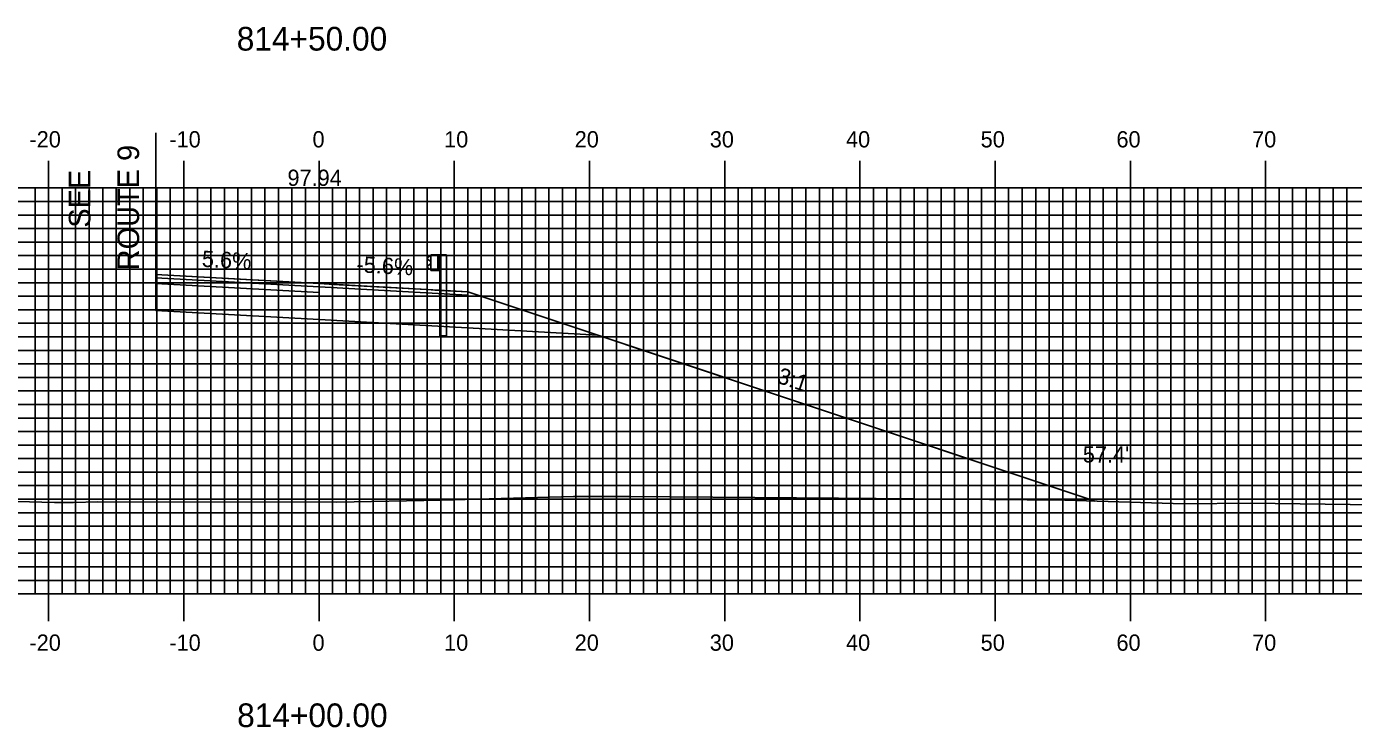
# Model space of a CAD drawing. Extents: x 2453 to 2796, y -1658 to -1438.
# Drawn here: x 2597.1 to 2695.2, y -1544.5 to -1492.7 of the extents above; entities that cross this region are included whole.
import ezdxf

# ---------------------------------------------------------------- set-up
doc = ezdxf.new("R2010")
doc.units = 0
for name, color, linetype in [('ANNOTATION', 7, 'Continuous'), ('D_Guardrail_Beam_Rt', 7, 'Continuous'), ('D_Roadway_Centerline', 7, 'Continuous'), ('D_Roadway_Centerline_Text', 7, 'Continuous'), ('D_Roadway_Edge_Shoulder', 7, 'Continuous'), ('D_Roadway_Edge_TW', 7, 'Continuous'), ('D_Roadway_Pavement', 7, 'Continuous'), ('D_Roadway_SlopeLines', 7, 'Continuous'), ('D_Roadway_SubGrade', 7, 'Continuous'), ('D_Text_Standard', 7, 'Continuous'), ('H_V ANNOTATION', 7, 'Continuous'), ('MAJOR', 7, 'Continuous'), ('MINOR', 7, 'Continuous'), ('S_Roadway_Centerline', 7, 'Continuous')]:
    doc.layers.add(name, color=color, linetype=linetype)

msp = doc.modelspace()

# ---------------------------------------------------------------- linework, layer by layer
at = {"layer": 'D_Guardrail_Beam_Rt'}
for p, q in [((2626.881, -1509.637), (2626.737, -1509.737)), ((2626.737, -1509.88), (2626.933, -1510.016)), ((2626.933, -1510.215), (2626.737, -1510.352)), ((2626.971, -1509.616), (2626.896, -1509.631)), ((2626.966, -1510.081), (2626.966, -1510.151)), ((2626.971, -1509.533), (2627.658, -1509.533)), ((2626.971, -1510.699), (2626.971, -1509.533)), ((2627.491, -1509.533), (2627.491, -1510.699)), ((2627.596, -1509.533), (2627.596, -1510.699)), ((2627.658, -1509.533), (2628.129, -1509.533)), ((2627.658, -1509.533), (2627.658, -1510.699)), ((2628.129, -1509.533), (2628.129, -1515.533)), ((2626.737, -1510.495), (2626.881, -1510.595)), ((2626.896, -1510.601), (2626.971, -1510.616)), ((2627.658, -1510.699), (2626.971, -1510.699)), ((2627.637, -1515.533), (2627.637, -1510.699)), ((2627.637, -1515.533), (2628.129, -1515.533))]:
    msp.add_line(p, q, dxfattribs=at)
for centre, major_axis, start_param, end_param in [((2626.788, -1509.809), (-0.0877, 0), 5.323254, 7.243116), ((2626.905, -1509.671), (-0.0417, 0), 4.907132, 5.323254), ((2626.887, -1510.081), (0.0789, 0), 0, 0.959931), ((2626.887, -1510.151), (0.0789, 0), 5.323254, 6.283185), ((2626.788, -1510.423), (-0.0877, 0), 5.323254, 7.243116), ((2626.905, -1510.561), (-0.0417, 0), 0.959931, 1.376053)]:
    msp.add_ellipse(centre, major_axis=major_axis, ratio=0.995501, start_param=start_param, end_param=end_param, dxfattribs=at)
at = {"layer": 'D_Roadway_Centerline'}
msp.add_lwpolyline([(2606.636, -1510.994), (2613.287, -1511.365), (2618.7, -1511.668), (2620.183, -1511.751), (2626.7, -1512.116), (2627.254, -1512.147), (2629.7, -1512.284), (2639.315, -1515.489), (2676.093, -1527.748)], dxfattribs=at)
at = {"layer": 'D_Roadway_Edge_Shoulder'}
for points in [[(2618.7, -1511.668), (2629.7, -1512.284), (2629.7, -1512.534), (2618.7, -1511.918)], [(2618.7, -1511.668), (2626.7, -1512.116), (2626.7, -1512.116), (2629.7, -1512.284), (2629.7, -1512.534), (2618.7, -1511.918)], [(2618.7, -1511.668), (2626.7, -1512.116), (2626.7, -1512.116), (2629.7, -1512.284), (2629.7, -1512.534), (2618.7, -1511.918)], [(2618.7, -1511.668), (2629.7, -1512.284), (2629.7, -1512.534), (2618.7, -1511.918)], [(2618.7, -1511.668), (2629.7, -1512.284), (2629.7, -1512.534), (2618.7, -1511.918)]]:
    msp.add_lwpolyline(points, close=True, dxfattribs=at)
at = {"layer": 'D_Roadway_Edge_TW'}
msp.add_lwpolyline([(2606.636, -1510.994), (2618.7, -1511.668), (2618.7, -1511.918), (2606.636, -1511.244)], close=True, dxfattribs=at)
msp.add_lwpolyline([(2606.636, -1510.994), (2618.7, -1511.668), (2618.7, -1511.918), (2606.636, -1511.244)], close=True, dxfattribs=at)
msp.add_lwpolyline([(2606.636, -1510.994), (2618.7, -1511.668), (2618.7, -1511.918), (2606.636, -1511.244)], close=True, dxfattribs=at)
msp.add_lwpolyline([(2606.636, -1510.994), (2618.7, -1511.668), (2618.7, -1511.918), (2606.636, -1511.244)], close=True, dxfattribs=at)
at = {"layer": 'D_Roadway_Pavement'}
msp.add_lwpolyline([(2606.636, -1511.244), (2618.7, -1511.918), (2618.7, -1512.335), (2606.636, -1511.66)], close=True, dxfattribs=at)
msp.add_lwpolyline([(2606.636, -1511.244), (2618.7, -1511.918), (2618.7, -1512.335), (2606.636, -1511.66)], close=True, dxfattribs=at)
msp.add_lwpolyline([(2606.636, -1511.244), (2618.7, -1511.918), (2618.7, -1512.335), (2606.636, -1511.66)], close=True, dxfattribs=at)
msp.add_lwpolyline([(2606.636, -1511.244), (2618.7, -1511.918), (2618.7, -1512.335), (2606.636, -1511.66)], close=True, dxfattribs=at)
msp.add_lwpolyline([(2618.7, -1511.918), (2618.7, -1512.335)], dxfattribs=at)
msp.add_lwpolyline([(2618.7, -1511.918), (2618.7, -1512.335)], dxfattribs=at)
msp.add_lwpolyline([(2618.7, -1511.918), (2618.7, -1512.335)], dxfattribs=at)
msp.add_lwpolyline([(2618.7, -1511.918), (2618.7, -1512.335)], dxfattribs=at)
msp.add_lwpolyline([(2618.7, -1511.918), (2618.7, -1512.335)], dxfattribs=at)
msp.add_lwpolyline([(2618.7, -1511.918), (2618.7, -1512.335)], dxfattribs=at)
msp.add_lwpolyline([(2618.7, -1511.918), (2618.7, -1512.335)], dxfattribs=at)
msp.add_lwpolyline([(2618.7, -1511.918), (2618.7, -1512.335)], dxfattribs=at)
msp.add_lwpolyline([(2618.7, -1511.918), (2618.7, -1512.335)], dxfattribs=at)
msp.add_lwpolyline([(2618.7, -1511.918), (2618.7, -1512.335)], dxfattribs=at)
msp.add_lwpolyline([(2618.7, -1511.918), (2618.7, -1512.335)], dxfattribs=at)
msp.add_lwpolyline([(2618.7, -1511.918), (2618.7, -1512.335)], dxfattribs=at)
msp.add_lwpolyline([(2618.7, -1511.918), (2618.7, -1512.335)], dxfattribs=at)
msp.add_lwpolyline([(2618.7, -1511.918), (2618.7, -1512.335)], dxfattribs=at)
at = {"layer": 'D_Roadway_SlopeLines'}
msp.add_lwpolyline([(2629.7, -1512.284), (2676.093, -1527.748)], dxfattribs=at)
msp.add_lwpolyline([(2629.7, -1512.284), (2676.093, -1527.748)], dxfattribs=at)
msp.add_lwpolyline([(2629.7, -1512.284), (2676.093, -1527.748)], dxfattribs=at)
msp.add_lwpolyline([(2629.7, -1512.284), (2676.093, -1527.748)], dxfattribs=at)
at = {"layer": 'D_Roadway_SubGrade'}
msp.add_line((2606.636, -1500.521), (2606.636, -1513.66), dxfattribs=at)
for points in [[(2606.636, -1511.66), (2618.7, -1512.335), (2618.7, -1514.335), (2606.636, -1513.66)], [(2606.636, -1511.66), (2618.7, -1512.335), (2618.7, -1514.335), (2606.636, -1513.66)], [(2606.636, -1511.66), (2618.7, -1512.335), (2618.7, -1514.335), (2606.636, -1513.66)], [(2606.636, -1511.66), (2618.7, -1512.335), (2618.7, -1514.335), (2606.636, -1513.66)], [(2618.7, -1512.335), (2618.7, -1511.918), (2629.7, -1512.534), (2629.7, -1512.284), (2639.315, -1515.489), (2618.7, -1514.335)]]:
    msp.add_lwpolyline(points, close=True, dxfattribs=at)
at = {"layer": 'MAJOR'}
for p, q in [((2598.7, -1502.6), (2598.7, -1504.604)), ((2608.7, -1502.6), (2608.7, -1504.604)), ((2618.7, -1502.6), (2618.7, -1504.604)), ((2628.7, -1502.6), (2628.7, -1504.604)), ((2638.7, -1502.6), (2638.7, -1504.604)), ((2648.7, -1502.6), (2648.7, -1504.604)), ((2658.7, -1502.6), (2658.7, -1504.604)), ((2668.7, -1502.6), (2668.7, -1504.604)), ((2678.7, -1502.6), (2678.7, -1504.604)), ((2688.7, -1502.6), (2688.7, -1504.604)), ((2478.7, -1504.604), (2758.7, -1504.604)), ((2478.7, -1504.604), (2758.7, -1504.604)), ((2598.7, -1534.604), (2598.7, -1504.604)), ((2608.7, -1534.604), (2608.7, -1504.604)), ((2618.7, -1534.604), (2618.7, -1504.604)), ((2628.7, -1534.604), (2628.7, -1504.604)), ((2638.7, -1534.604), (2638.7, -1504.604)), ((2648.7, -1534.604), (2648.7, -1504.604)), ((2658.7, -1534.604), (2658.7, -1504.604)), ((2668.7, -1534.604), (2668.7, -1504.604)), ((2678.7, -1534.604), (2678.7, -1504.604)), ((2688.7, -1534.604), (2688.7, -1504.604)), ((2478.7, -1509.604), (2758.7, -1509.604)), ((2478.7, -1514.604), (2758.7, -1514.604)), ((2478.7, -1519.604), (2758.7, -1519.604)), ((2478.7, -1524.604), (2758.7, -1524.604)), ((2478.7, -1529.604), (2758.7, -1529.604)), ((2478.7, -1534.604), (2758.7, -1534.604)), ((2478.7, -1534.604), (2758.7, -1534.604)), ((2598.7, -1536.608), (2598.7, -1534.604)), ((2608.7, -1536.608), (2608.7, -1534.604)), ((2618.7, -1536.608), (2618.7, -1534.604)), ((2628.7, -1536.608), (2628.7, -1534.604)), ((2638.7, -1536.608), (2638.7, -1534.604)), ((2648.7, -1536.608), (2648.7, -1534.604)), ((2658.7, -1536.608), (2658.7, -1534.604)), ((2668.7, -1536.608), (2668.7, -1534.604)), ((2678.7, -1536.608), (2678.7, -1534.604)), ((2688.7, -1536.608), (2688.7, -1534.604))]:
    msp.add_line(p, q, dxfattribs=at)
at = {"layer": 'MINOR'}
for p, q in [((2597.7, -1534.604), (2597.7, -1504.604)), ((2599.7, -1534.604), (2599.7, -1504.604)), ((2600.7, -1534.604), (2600.7, -1504.604)), ((2601.7, -1534.604), (2601.7, -1504.604)), ((2602.7, -1534.604), (2602.7, -1504.604)), ((2603.7, -1534.604), (2603.7, -1504.604)), ((2604.7, -1534.604), (2604.7, -1504.604)), ((2605.7, -1534.604), (2605.7, -1504.604)), ((2606.7, -1534.604), (2606.7, -1504.604)), ((2607.7, -1534.604), (2607.7, -1504.604)), ((2609.7, -1534.604), (2609.7, -1504.604)), ((2610.7, -1534.604), (2610.7, -1504.604)), ((2611.7, -1534.604), (2611.7, -1504.604)), ((2612.7, -1534.604), (2612.7, -1504.604)), ((2613.7, -1534.604), (2613.7, -1504.604)), ((2614.7, -1534.604), (2614.7, -1504.604)), ((2615.7, -1534.604), (2615.7, -1504.604)), ((2616.7, -1534.604), (2616.7, -1504.604)), ((2617.7, -1534.604), (2617.7, -1504.604)), ((2619.7, -1534.604), (2619.7, -1504.604)), ((2620.7, -1534.604), (2620.7, -1504.604)), ((2621.7, -1534.604), (2621.7, -1504.604)), ((2622.7, -1534.604), (2622.7, -1504.604)), ((2623.7, -1534.604), (2623.7, -1504.604)), ((2624.7, -1534.604), (2624.7, -1504.604)), ((2625.7, -1534.604), (2625.7, -1504.604)), ((2626.7, -1534.604), (2626.7, -1504.604)), ((2627.7, -1534.604), (2627.7, -1504.604)), ((2629.7, -1534.604), (2629.7, -1504.604)), ((2630.7, -1534.604), (2630.7, -1504.604)), ((2631.7, -1534.604), (2631.7, -1504.604)), ((2632.7, -1534.604), (2632.7, -1504.604)), ((2633.7, -1534.604), (2633.7, -1504.604)), ((2634.7, -1534.604), (2634.7, -1504.604)), ((2635.7, -1534.604), (2635.7, -1504.604)), ((2636.7, -1534.604), (2636.7, -1504.604)), ((2637.7, -1534.604), (2637.7, -1504.604)), ((2639.7, -1534.604), (2639.7, -1504.604)), ((2640.7, -1534.604), (2640.7, -1504.604)), ((2641.7, -1534.604), (2641.7, -1504.604)), ((2642.7, -1534.604), (2642.7, -1504.604)), ((2643.7, -1534.604), (2643.7, -1504.604)), ((2644.7, -1534.604), (2644.7, -1504.604)), ((2645.7, -1534.604), (2645.7, -1504.604)), ((2646.7, -1534.604), (2646.7, -1504.604)), ((2647.7, -1534.604), (2647.7, -1504.604)), ((2649.7, -1534.604), (2649.7, -1504.604)), ((2650.7, -1534.604), (2650.7, -1504.604)), ((2651.7, -1534.604), (2651.7, -1504.604)), ((2652.7, -1534.604), (2652.7, -1504.604)), ((2653.7, -1534.604), (2653.7, -1504.604)), ((2654.7, -1534.604), (2654.7, -1504.604)), ((2655.7, -1534.604), (2655.7, -1504.604)), ((2656.7, -1534.604), (2656.7, -1504.604)), ((2657.7, -1534.604), (2657.7, -1504.604)), ((2659.7, -1534.604), (2659.7, -1504.604)), ((2660.7, -1534.604), (2660.7, -1504.604)), ((2661.7, -1534.604), (2661.7, -1504.604)), ((2662.7, -1534.604), (2662.7, -1504.604)), ((2663.7, -1534.604), (2663.7, -1504.604)), ((2664.7, -1534.604), (2664.7, -1504.604)), ((2665.7, -1534.604), (2665.7, -1504.604)), ((2666.7, -1534.604), (2666.7, -1504.604)), ((2667.7, -1534.604), (2667.7, -1504.604)), ((2669.7, -1534.604), (2669.7, -1504.604)), ((2670.7, -1534.604), (2670.7, -1504.604)), ((2671.7, -1534.604), (2671.7, -1504.604)), ((2672.7, -1534.604), (2672.7, -1504.604)), ((2673.7, -1534.604), (2673.7, -1504.604)), ((2674.7, -1534.604), (2674.7, -1504.604)), ((2675.7, -1534.604), (2675.7, -1504.604)), ((2676.7, -1534.604), (2676.7, -1504.604)), ((2677.7, -1534.604), (2677.7, -1504.604)), ((2679.7, -1534.604), (2679.7, -1504.604)), ((2680.7, -1534.604), (2680.7, -1504.604)), ((2681.7, -1534.604), (2681.7, -1504.604)), ((2682.7, -1534.604), (2682.7, -1504.604)), ((2683.7, -1534.604), (2683.7, -1504.604)), ((2684.7, -1534.604), (2684.7, -1504.604)), ((2685.7, -1534.604), (2685.7, -1504.604)), ((2686.7, -1534.604), (2686.7, -1504.604)), ((2687.7, -1534.604), (2687.7, -1504.604)), ((2689.7, -1534.604), (2689.7, -1504.604)), ((2690.7, -1534.604), (2690.7, -1504.604)), ((2691.7, -1534.604), (2691.7, -1504.604)), ((2692.7, -1534.604), (2692.7, -1504.604)), ((2693.7, -1534.604), (2693.7, -1504.604)), ((2694.7, -1534.604), (2694.7, -1504.604)), ((2478.7, -1505.604), (2758.7, -1505.604)), ((2478.7, -1506.604), (2758.7, -1506.604)), ((2478.7, -1507.604), (2758.7, -1507.604)), ((2478.7, -1508.604), (2758.7, -1508.604)), ((2478.7, -1510.604), (2758.7, -1510.604)), ((2478.7, -1511.604), (2758.7, -1511.604)), ((2478.7, -1512.604), (2758.7, -1512.604)), ((2478.7, -1513.604), (2758.7, -1513.604)), ((2478.7, -1515.604), (2758.7, -1515.604)), ((2478.7, -1516.604), (2758.7, -1516.604)), ((2478.7, -1517.604), (2758.7, -1517.604)), ((2478.7, -1518.604), (2758.7, -1518.604)), ((2478.7, -1520.604), (2758.7, -1520.604)), ((2478.7, -1521.604), (2758.7, -1521.604)), ((2478.7, -1522.604), (2758.7, -1522.604)), ((2478.7, -1523.604), (2758.7, -1523.604)), ((2478.7, -1525.604), (2758.7, -1525.604)), ((2478.7, -1526.604), (2758.7, -1526.604)), ((2478.7, -1527.604), (2758.7, -1527.604)), ((2478.7, -1528.604), (2758.7, -1528.604)), ((2478.7, -1530.604), (2758.7, -1530.604)), ((2478.7, -1531.604), (2758.7, -1531.604)), ((2478.7, -1532.604), (2758.7, -1532.604)), ((2478.7, -1533.604), (2758.7, -1533.604))]:
    msp.add_line(p, q, dxfattribs=at)
at = {"layer": 'S_Roadway_Centerline'}
msp.add_lwpolyline([(2590.783, -1527.622), (2599.132, -1527.855), (2600.535, -1527.836), (2602.347, -1527.801), (2620.014, -1527.814), (2627.732, -1527.673), (2637.526, -1527.417), (2641.628, -1527.416), (2657.105, -1527.524), (2673.853, -1527.681), (2682.662, -1527.946), (2687.561, -1527.907), (2700.509, -1528.071)], dxfattribs=at)

# ---------------------------------------------------------------- texts
at = {"layer": 'ANNOTATION'}
for s, height, rotation, p in [('ROUTE 9', 1.6, 90, (2605.394, -1510.688)), ('SEE', 1.6, 90, (2601.794, -1507.538)), ('5.6%', 1.2, 356.8012, (2610.013, -1510.423)), ('-5.6%', 1.2, 356.79478, (2621.447, -1510.827)), ('3:1', 1.2, 341.56505, (2652.5, -1518.976))]:
    msp.add_text(s, height=height, rotation=rotation, dxfattribs=at).set_placement(p)
at = {"layer": 'D_Roadway_Centerline_Text'}
msp.add_text('97.94', height=1.2, dxfattribs=at).set_placement((2616.367, -1504.448))
at = {"layer": 'D_Text_Standard'}
msp.add_text("57.4'", height=1.2, dxfattribs=at).set_placement((2675.186, -1524.893))
at = {"layer": 'H_V ANNOTATION'}
for s, height, p in [('814+50.00', 1.75, (2612.614, -1494.448)), ('-20', 1.2, (2597.287, -1501.604)), ('-10', 1.2, (2607.63, -1501.604)), ('0', 1.2, (2618.218, -1501.604)), ('10', 1.2, (2627.95, -1501.604)), ('20', 1.2, (2637.608, -1501.604)), ('30', 1.2, (2647.597, -1501.604)), ('40', 1.2, (2657.672, -1501.604)), ('50', 1.2, (2667.629, -1501.604)), ('60', 1.2, (2677.672, -1501.604)), ('70', 1.2, (2687.704, -1501.604)), ('-20', 1.2, (2597.287, -1538.804)), ('-10', 1.2, (2607.63, -1538.804)), ('0', 1.2, (2618.218, -1538.804)), ('10', 1.2, (2627.95, -1538.804)), ('20', 1.2, (2637.608, -1538.804)), ('30', 1.2, (2647.597, -1538.804)), ('40', 1.2, (2657.672, -1538.804)), ('50', 1.2, (2667.629, -1538.804)), ('60', 1.2, (2677.672, -1538.804)), ('70', 1.2, (2687.704, -1538.804)), ('814+00.00', 1.75, (2612.645, -1544.448))]:
    msp.add_text(s, height=height, dxfattribs=at).set_placement(p)

doc.saveas('drawing.dxf')
